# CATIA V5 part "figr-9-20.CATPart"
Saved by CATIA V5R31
Part number: Part3
Bounding box of the stored display mesh (mm): x -112 to 0, y -101.683 to 100, z -80.304 to 44.415
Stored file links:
  D:\PROJECTS\Project 2021\US EDITION\CATIA V5 6R 2021\Resources\Part Files\c09_catia_v5_6r2021_prt\c09_catia_v5_6r2021_prt\figr-9-20.CATPart
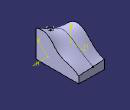
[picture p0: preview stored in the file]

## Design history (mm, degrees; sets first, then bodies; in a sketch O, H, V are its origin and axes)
Set1
  Plane1: type Offset, RefPlane yz-plane, Offset -112
  Plane2: type Offset, RefPlane yz-plane, Offset -63
  Plane3: type Normal, Curve Sketch4, RefPoint vertex of Sketch4
Body1 (main body)
  Sketch1 on yz-plane, origin (0, 0, 0), H (0, 1, 0), V (0, 0, 1)
    spline S1 through (-92.6897, 40.1119) (-30, 30) (10, -10) (60, -30) (97.3103, -50.3041)
    line L1 (97.3103, -50.3041) -> (97.3103, -80.3041)
    line L2 (97.3103, -80.3041) -> (-92.6897, -80.3041)
    line L3 (-92.6897, -80.3041) -> (-92.6897, 40.1119)
    point P3 (-92.6897, 40.1119)
    point P4 (97.3103, -50.3041)
    point P5 (-92.6897, 40.1119)
    point P6 (97.3103, -50.3041)
    vertical: L1 V, L3 V
    horizontal: L2 H
    coincidence: P5 P3, P6 P4
  Sketch2 on Plane1, origin (-112, 0, 0), H (0, 1, 0), V (0, 0, 1)
    spline S1 through (-90, -30) (-70, 10) (-20, 40) (40, 0) (100, -40)
    line L1 (100, -40) -> (100, -80)
    line L2 (100, -80) -> (-90, -80)
    line L3 (-90, -80) -> (-90, -30)
    point P3 (-90, -30)
    point P4 (100, -40)
    point P5 (40, 0)
    point P6 (-90, -30)
    point P7 (100, -40)
    coincidence: P5 H, P6 P3, P7 P4
    vertical: L1 V, L3 V
    horizontal: L2 H
  Loft1: Sections (Sketch1; Sketch2)
  Sketch3 on Plane3, origin (0, -40.1726, -44.9298), H (1, 0, 0), V (0, -0.7455, 0.6665)
    point P1 (-63, 68.4187)
    line L1 (-63, 68.4187) -> (-75.2117, 62.4925)
    line L2 (-75.2117, 62.4925) -> (-79.6266, 71.5898)
    line L3 (-79.6266, 71.5898) -> (-57.1205, 82.5119)
    line L4 (-57.1205, 82.5119) -> (-52.7056, 73.4145)
    point P5 (-52.7056, 73.4145)
    line L5 (-52.7056, 73.4145) -> (-63, 68.4187)
    reference projected point E1 (-63, 68.4187) from vertex of Sketch4
    perpendicularity: L2 L1
    parallelism: L3 L1, L4 L2, L5 L1
    coincidence: P5 L1, P1 E1
  Sketch4 on Plane2, origin (-63, 0, 0), H (0, 1, 0), V (0, 0, 1)
    intersected curve E1 from face of Loft1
